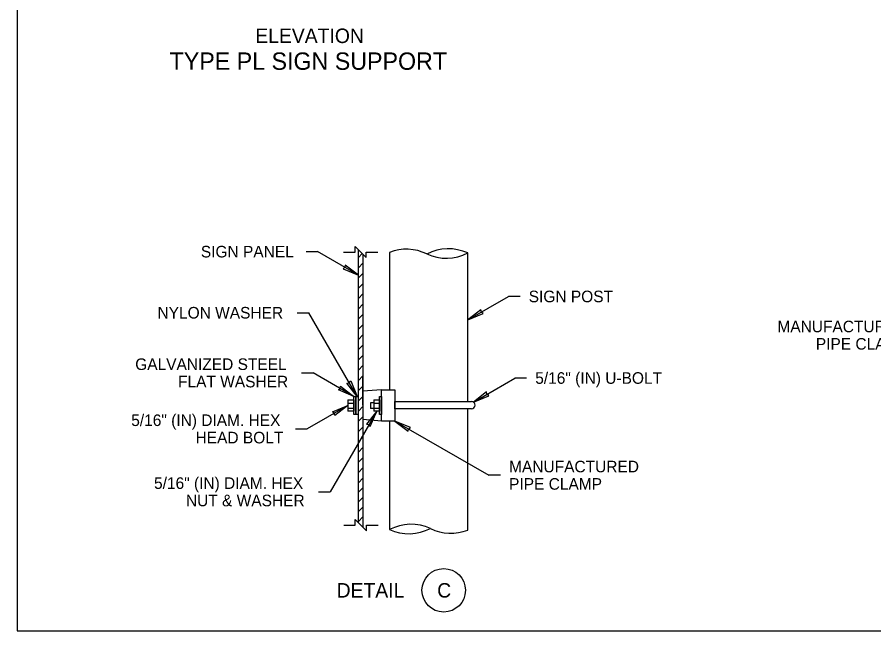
# Model space of a CAD drawing. Extents: x 99862 to 103151, y 100000 to 105076.
# Drawn here: x 99862 to 101046, y 100000 to 100847 of the extents above; entities that cross this region are included whole.
import ezdxf

# ---------------------------------------------------------------- set-up
doc = ezdxf.new("R2010")
doc.units = 0
for name, color, linetype in [('Level 1', 7, 'Continuous'), ('Level 15', 7, 'Continuous'), ('Level 2', 7, 'Continuous'), ('Level 20', 7, 'Continuous'), ('Level 27', 7, 'Continuous'), ('Level 3', 7, 'Continuous'), ('Level 60', 7, 'Continuous')]:
    doc.layers.add(name, color=color, linetype=linetype)

msp = doc.modelspace()

# ---------------------------------------------------------------- linework, layer by layer
at = {"layer": 'Level 1'}
for p, q in [((100333.6, 100524.4), (100334.5, 100525.2)), ((100333.6, 100515.4), (100339, 100520.7)), ((100333.6, 100501.2), (100339.8, 100507.4)), ((100333.6, 100487.1), (100339.8, 100493.2)), ((100333.6, 100472.9), (100339.8, 100479.1)), ((100333.6, 100458.8), (100339.8, 100464.9)), ((100333.6, 100444.6), (100339.8, 100450.8)), ((100333.6, 100430.5), (100339.8, 100436.6)), ((100333.6, 100416.4), (100339.8, 100422.5)), ((100333.6, 100402.2), (100339.8, 100408.4)), ((100333.6, 100388.1), (100339.8, 100394.2)), ((100333.6, 100373.9), (100339.8, 100380.1)), ((100333.6, 100359.8), (100339.8, 100365.9)), ((100333.6, 100345.6), (100339.8, 100351.8)), ((100333.6, 100331.5), (100339.8, 100337.6)), ((100333.6, 100317.4), (100339.8, 100323.5)), ((100333.6, 100303.2), (100339.8, 100309.4)), ((100333.6, 100289.1), (100339.8, 100295.2)), ((100333.6, 100274.9), (100339.8, 100281.1)), ((100333.6, 100260.8), (100339.8, 100266.9)), ((100333.6, 100246.6), (100339.8, 100252.8)), ((100333.6, 100232.5), (100339.8, 100238.6)), ((100333.6, 100218.4), (100339.8, 100224.5)), ((100333.6, 100204.2), (100339.8, 100210.4)), ((100333.6, 100191.1), (100339.8, 100197.2)), ((100333.6, 100177.6), (100339.8, 100183.7)), ((100333.6, 100164.4), (100339.8, 100170.6)), ((100333.6, 100150.7), (100339.8, 100156.9))]:
    msp.add_line(p, q, dxfattribs=at)
msp.add_lwpolyline([(99862, 99999.5), (103151, 99999.5), (103151, 102075.5), (99862, 102075.5)], close=True, dxfattribs=at)
for points in [[(100333.6, 100148.9), (100333.6, 100526)], [(100339.8, 100519.9), (100339.8, 100142.8)]]:
    msp.add_lwpolyline(points, dxfattribs=at)
for centre, radius, start, end in [((100399.8, 100463.2), 63.6, 63.587, 111.4161), ((100458, 100463.2), 64.2, 65.3773, 117.689), ((100454.9, 100578.3), 64, 245.3003, 297.766), ((100406.5, 100082.8), 64, 65.3003, 117.766), ((100403.4, 100197.9), 64.2, 245.3773, 297.689), ((100461.5, 100198), 63.6, 243.587, 291.4161)]:
    msp.add_arc(centre, radius, start, end, dxfattribs=at)
at = {"layer": 'Level 15'}
for p, q in [((100261.3, 100523.4), (100277.3, 100523.4)), ((100333.6, 100490.9), (100277.3, 100523.4)), ((100484.7, 100429), (100541, 100461.5)), ((100557, 100461.5), (100541, 100461.5)), ((100249, 100439), (100265, 100439)), ((100331.8, 100323.4), (100265, 100439)), ((100255.1, 100355.9), (100271.1, 100355.9)), ((100327.4, 100323.4), (100271.1, 100355.9)), ((100492.5, 100315.6), (100550, 100348.8)), ((100566, 100348.8), (100550, 100348.8)), ((100319.2, 100311), (100262.9, 100278.5)), ((100358.9, 100303.2), (100294.5, 100191.6)), ((100384.1, 100289.4), (100513.9, 100214.5)), ((100246.9, 100278.5), (100262.9, 100278.5)), ((100529.9, 100214.5), (100513.9, 100214.5)), ((100278.5, 100191.6), (100294.5, 100191.6))]:
    msp.add_line(p, q, dxfattribs=at)
for points in [[(100313, 100522.9), (100329, 100522.9), (100329, 100530.6), (100344.5, 100515.1), (100344.5, 100522.9), (100360.5, 100522.9)], [(100313.3, 100145.5), (100329.3, 100145.5), (100329.3, 100153.2), (100344.8, 100137.8), (100344.8, 100145.5), (100360.8, 100145.5)]]:
    msp.add_lwpolyline(points, dxfattribs=at)
for points in [[(100333.6, 100490.9), (100315.3, 100504.9), (100314.8, 100501.8), (100312.4, 100499.7)], [(100484.7, 100429), (100506, 100437.8), (100503.6, 100439.9), (100503, 100443)], [(100331.8, 100323.4), (100317.8, 100341.7), (100320.9, 100342.3), (100323, 100344.7)], [(100327.4, 100323.4), (100306.1, 100332.3), (100308.5, 100334.3), (100309.1, 100337.4)], [(100492.5, 100315.6), (100513.7, 100324.4), (100511.3, 100326.5), (100510.7, 100329.6)], [(100319.2, 100311), (100300.9, 100297), (100300.3, 100300.1), (100297.9, 100302.2)], [(100358.9, 100303.2), (100344.9, 100285), (100348, 100284.4), (100350.1, 100282)], [(100384.1, 100289.4), (100402.4, 100275.4), (100403, 100278.5), (100405.4, 100280.6)]]:
    msp.add_lwpolyline(points, close=True, dxfattribs=at)
at = {"layer": 'Level 2'}
for points in [[(100376.6, 100522.4), (100376.6, 100332.6)], [(100484.7, 100316.4), (100484.7, 100521.6)], [(100484.7, 100138.8), (100484.7, 100306.3)], [(100376.6, 100289.4), (100376.6, 100139.5)]]:
    msp.add_lwpolyline(points, dxfattribs=at)
at = {"layer": 'Level 20'}
msp.add_circle((100451.5, 100055.5), 30, dxfattribs=at)
at = {"layer": 'Level 27'}
msp.add_lwpolyline([(100339.8, 100311.4), (100339.8, 100351.2)], dxfattribs=at)
at = {"layer": 'Level 3'}
for p, q in [((100319.2, 100318.7), (100319.2, 100303.2)), ((100354.8, 100314.7), (100350.3, 100314.7)), ((100350.3, 100314.7), (100350.3, 100306.5)), ((100354.8, 100318.7), (100354.8, 100303.2)), ((100354.8, 100306.5), (100350.3, 100306.5))]:
    msp.add_line(p, q, dxfattribs=at)
for points in [[(100365.7, 100332.6), (100339.8, 100330.5)], [(100319.2, 100318.7), (100327.4, 100318.7), (100327.4, 100303.2), (100319.2, 100303.2)], [(100319.2, 100314), (100327.4, 100314)], [(100354.8, 100318.7), (100363, 100318.7), (100363, 100303.2), (100354.8, 100303.2)], [(100354.8, 100314), (100363, 100314)], [(100489.8, 100306.3), (100384.1, 100306.3), (100384.1, 100316.4), (100489.8, 100316.4)], [(100319.2, 100307.3), (100327.4, 100307.3)], [(100354.8, 100307.3), (100363, 100307.3)], [(100365.7, 100289.4), (100339.8, 100291.4)]]:
    msp.add_lwpolyline(points, dxfattribs=at)
for points in [[(100365.7, 100332.6), (100384.1, 100332.6), (100384.1, 100289.4), (100365.7, 100289.4)], [(100327.4, 100323.4), (100330.1, 100323.4), (100330.1, 100298.5), (100327.4, 100298.5)], [(100330.1, 100323.4), (100333.5, 100323.4), (100333.5, 100298.5), (100330.1, 100298.5)], [(100363, 100323.4), (100365.7, 100323.4), (100365.7, 100298.5), (100363, 100298.5)]]:
    msp.add_lwpolyline(points, close=True, dxfattribs=at)
msp.add_arc((100489.8, 100311.3), 5.06, 269.2645, 89.2645, dxfattribs=at)
at = {"layer": 'Level 60'}
msp.add_line((99862, 99999.5), (99862, 99999.5), dxfattribs=at)
msp.add_line((99862, 99999.5), (99862, 99999.5), dxfattribs=at)

# ---------------------------------------------------------------- texts
at = {"layer": 'Level 20'}
for s, height, p in [('ELEVATION', 20, (100191.1, 100811.6)), ('TYPE PL SIGN SUPPORT', 24, (100072.7, 100774.6)), ('SIGN PANEL', 16, (100115.9, 100515.4)), ('SIGN POST', 16, (100569, 100453.5)), ('NYLON WASHER ', 16, (100056, 100431)), ('MANUFACTURED', 16, (100912.7, 100412)), ('PIPE CLAMP', 16, (100965.8, 100388)), ('GALVANIZED STEEL ', 16, (100025.2, 100359.9)), ('5/16" (IN) U-BOLT', 16, (100578, 100340.8)), ('FLAT WASHER', 16, (100084.4, 100335.9)), ('5/16" (IN) DIAM. HEX', 16, (100019.7, 100282.5)), ('HEAD BOLT', 16, (100108.6, 100258.5)), ('MANUFACTURED', 16, (100541.9, 100218.5)), ('5/16" (IN) DIAM. HEX', 16, (100051.2, 100195.6)), ('PIPE CLAMP', 16, (100541.9, 100194.5)), ('NUT & WASHER', 16, (100095.3, 100171.6)), ('DETAIL', 20, (100303.5, 100045.5)), ('C', 20, (100442.5, 100045.5))]:
    msp.add_text(s, height=height, dxfattribs=at).set_placement(p)

doc.saveas('drawing.dxf')
